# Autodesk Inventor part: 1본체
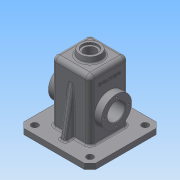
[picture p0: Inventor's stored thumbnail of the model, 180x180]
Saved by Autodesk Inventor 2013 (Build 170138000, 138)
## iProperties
Created: 2016-02
Part Number: 1본체
Material: 일반
Document SubType Name: Modeling
Designer: Administrator
Density: 1 g/cm^3
Author: Administrator
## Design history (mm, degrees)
sketch "스케치1"
  geometry: L1 (-65, 65)-(65, 65); L2 (65, 65)-(65, -65); L3 (65, -65)-(-65, -65); L4 (-65, -65)-(-65, 65); L5 (-65, 65)-(65, -65); 2 further points
  constraints: 10 end point, 2 parallel, 1 coincident, 1 horizontal, 1 midpoint, 1 perpendicular
  dimensions: "d0" = 130 distance of L1.end L2.end; "d2" = 130 distance of L1.start L1.end
extrude "돌출1" new body sketch "스케치1" distance "d3" = 10; taper "d4" = 0 deg
chamfer "모따기1" distance "d5" = 10; stored, may be unused: second distance "d6" = 2, angle "d7" = 45 deg
sketch "스케치2"
  geometry: C1 r 6 at (-50, 50); 1 further point
  constraints: 1 centre point
  dimensions: "d8" = 50 horizontal distance of point (0, 0) C1.centre; "d9" = 50 horizontal distance of point (0, 0) C1.centre; "d10" = 12 diameter of C1
extrude "돌출2" cut sketch "스케치2" stored distance "d11" = 10; taper "d12" = 0 deg
sketch "스케치3"
  geometry: L1 (65, -55)-(55, -65) reference; L2 (-35, 35)-(35, 35); L3 (35, 35)-(35, -35); L4 (35, -35)-(-35, -35); L5 (-35, -35)-(-35, 35); L6 (-35, 35)-(35, -35); 2 further points
  constraints: 10 end point, 2 parallel, 2 perpendicular, 1 coincident, 1 horizontal, 1 midpoint
  dimensions: "d19" = 70 distance of L2.end L3.end
extrude "돌출3" join sketch "스케치3" distance "d21" = 110; taper "d22" = 0 deg
sketch "스케치4"
  geometry: L1 (35, -35)-(35, 35) reference; L2 (35, 35)-(-35, 35) reference; L3 (-35, 35)-(-35, -35) reference; L4 (-35, -35)-(35, -35) reference; L5 (-30, 30)-(30, 30); L6 (30, 30)-(30, -30); L7 (30, -30)-(-30, -30); L8 (-30, -30)-(-30, 30); 1 further point
  constraints: 8 end point, 3 other
  dimensions: "d23" = 5 distance between parallel lines of L1 L6
extrude "돌출4" cut sketch "스케치4" distance "d24" = 115; taper "d25" = 0 deg
sketch "스케치5"
  geometry: L1 (0, 0)-(-110, 0) reference; L2 (10, 35)-(-45, 35); C1 r 27.5 at (-45, 35)
  constraints: 2 end point, 1 centre point, 1 coincident, 1 parallel
  dimensions: "d26" = 55 distance of L2.start L2.end; "d27" = 55 diameter of C1
extrude "돌출5" join sketch "스케치5" distance "d28" = 13; taper "d29" = 0 deg
sketch "스케치6"
  geometry: L1 (0, 0)-(-22.5, 0); C1 r 27.5 at (0, 0) reference; 2 further points
  constraints: 2 end point, 1 coincident, 1 horizontal
  dimensions: "d30" = 22.5 distance of L1.start L1.end
hole "구멍1" sketch "스케치6" at (-22.5, 0) diameter "d31" = 3.242; stored, may be unused: countersink angle "d35" = 90 deg, drill point angle "d37" = 118 deg; dims "d32" = 8, "d33" = 4, "d34" = 2, "d36" = 10
sketch "스케치7"
  geometry: C1 r 27.5 at (0, 0) reference; C2 r 16 at (0, 0); 1 further point
  constraints: 1 centre point, 1 coincident
  dimensions: "d42" = 32 diameter of C2
extrude "돌출6" cut sketch "스케치7" stored distance "d44" = 13; taper "d45" = 0 deg
sketch "스케치8"
  geometry: L1 (-30, 0)-(-30, 115) reference; L2 (-48, 71)-(-30, 71) reference; L3 (-35, 82.5)-(-48, 82.5) reference; L4 (-30, 82.5)-(-23, 75.5); L5 (-23, 75.5)-(-23, 71); L6 (-23, 71)-(-30, 71); L7 (-35, 27.5)-(-48, 27.5) reference; L8 (-30, 82.5)-(-30, 71); L9 (-48, 39)-(-48, 71) reference; L10 (-48, 55)-(-30, 55); 1 further point
  constraints: 10 end point, 4 perpendicular, 2 point on line, 1 midpoint
  dimensions: "d46" = 7 distance between parallel lines of L5 L1; "d47" = 135 deg angle of L1 L4; "d48" = 55 distance from line of L4.start L7
revolve "회전1" sketch "스케치8" stored, may be unused: angle "d49" = 90 deg
sketch "스케치9"
  geometry: C1 r 27.5 at (0, 0) reference; C2 r 16 at (0, 0); 1 further point
  constraints: 1 centre point, 1 coincident
  dimensions: "d51" = 32 diameter of C2
extrude "돌출7" cut sketch "스케치9" stored distance "d53" = 13; taper "d54" = 0 deg
chamfer "모따기2" distance "d55" = 1; stored, may be unused: second distance "d56" = 2, angle "d57" = 45 deg
sketch "스케치10"
  geometry: C1 r 20 at (0, 0); 1 further point
  constraints: 1 centre point, 1 coincident
  dimensions: "d59" = 40 diameter of C1
extrude "돌출8" join sketch "스케치10" distance "d61" = 10; taper "d62" = -10 deg
sketch "스케치11"
  geometry: C1 r 18.237 at (0, 0) reference; C2 r 14 at (0, 0)
  constraints: 1 centre point, 1 coincident
  dimensions: "d63" = 28 diameter of C2
extrude "돌출9" cut sketch "스케치11" distance "d65" = 4; taper "d66" = 0 deg
sketch "스케치12"
  geometry: C1 r 14 at (0, 0) reference; C2 r 10.5 at (0, 0)
  constraints: 1 centre point, 1 coincident
  dimensions: "d67" = 21 diameter of C2
extrude "돌출10" cut sketch "스케치12" stored distance "d69" = 4; taper "d70" = 0 deg
fillet "모깎기4" dims "d71" = 3
sketch "스케치13"
  geometry: L1 (35, 10)-(35, 120) reference; L2 (44, 10)-(56, 10) reference; L3 (55, 10)-(-55, 10) reference; L4 (35, 95.069)-(50, 10); L5 (65, 10)-(65, 0) reference; L6 (35, 95.069)-(35, 10); L7 (35, 10)-(50, 10); 1 further point
  constraints: 6 end point, 2 collinear, 2 point on line
  dimensions: "d72" = 10 deg angle of L5 L4; "d73" = 15 distance from line of L4.end L5
extrude "돌출11" join sketch "스케치13" stored distance "d74" = 10; taper "d75" = 0 deg
fillet "모깎기5" dims "d76" = 8
fillet "모깎기6" dims "d77" = 8
fillet "모깎기7" dims "d78" = 0.5
fillet "모깎기8" dims "d79" = 0.5
fillet "모깎기9" dims "d80" = 3
fillet "모깎기10" dims "d81" = 3
fillet "모깎기11" dims "d82" = 3
fillet "모깎기12" dims "d83" = 3
fillet "모깎기13" dims "d84" = 3
node "작업 평면1"
sketch "스케치14"
  geometry: L1 (-18, 8.763)-(-18, 45.237) reference; C1 r 17 at (57, 27) reference; 2 further points
  constraints: 1 horizontal alignment, 1 other
  dimensions: "d86" = 30 distance from line of point (12, 27) L1
feature "엠보싱1" sketch "스케치14" dims "d87" = 0.5, "d88" = 0
node "솔리드1"
pattern_linear "직사각형 패턴1" dims "d15" = 100
pattern_circular "원형 패턴1" dims angle "d39" = 360 deg
mirror "대칭1"
mirror "대칭2"
mirror "대칭3"
other parameters: "d85" = 55.25
